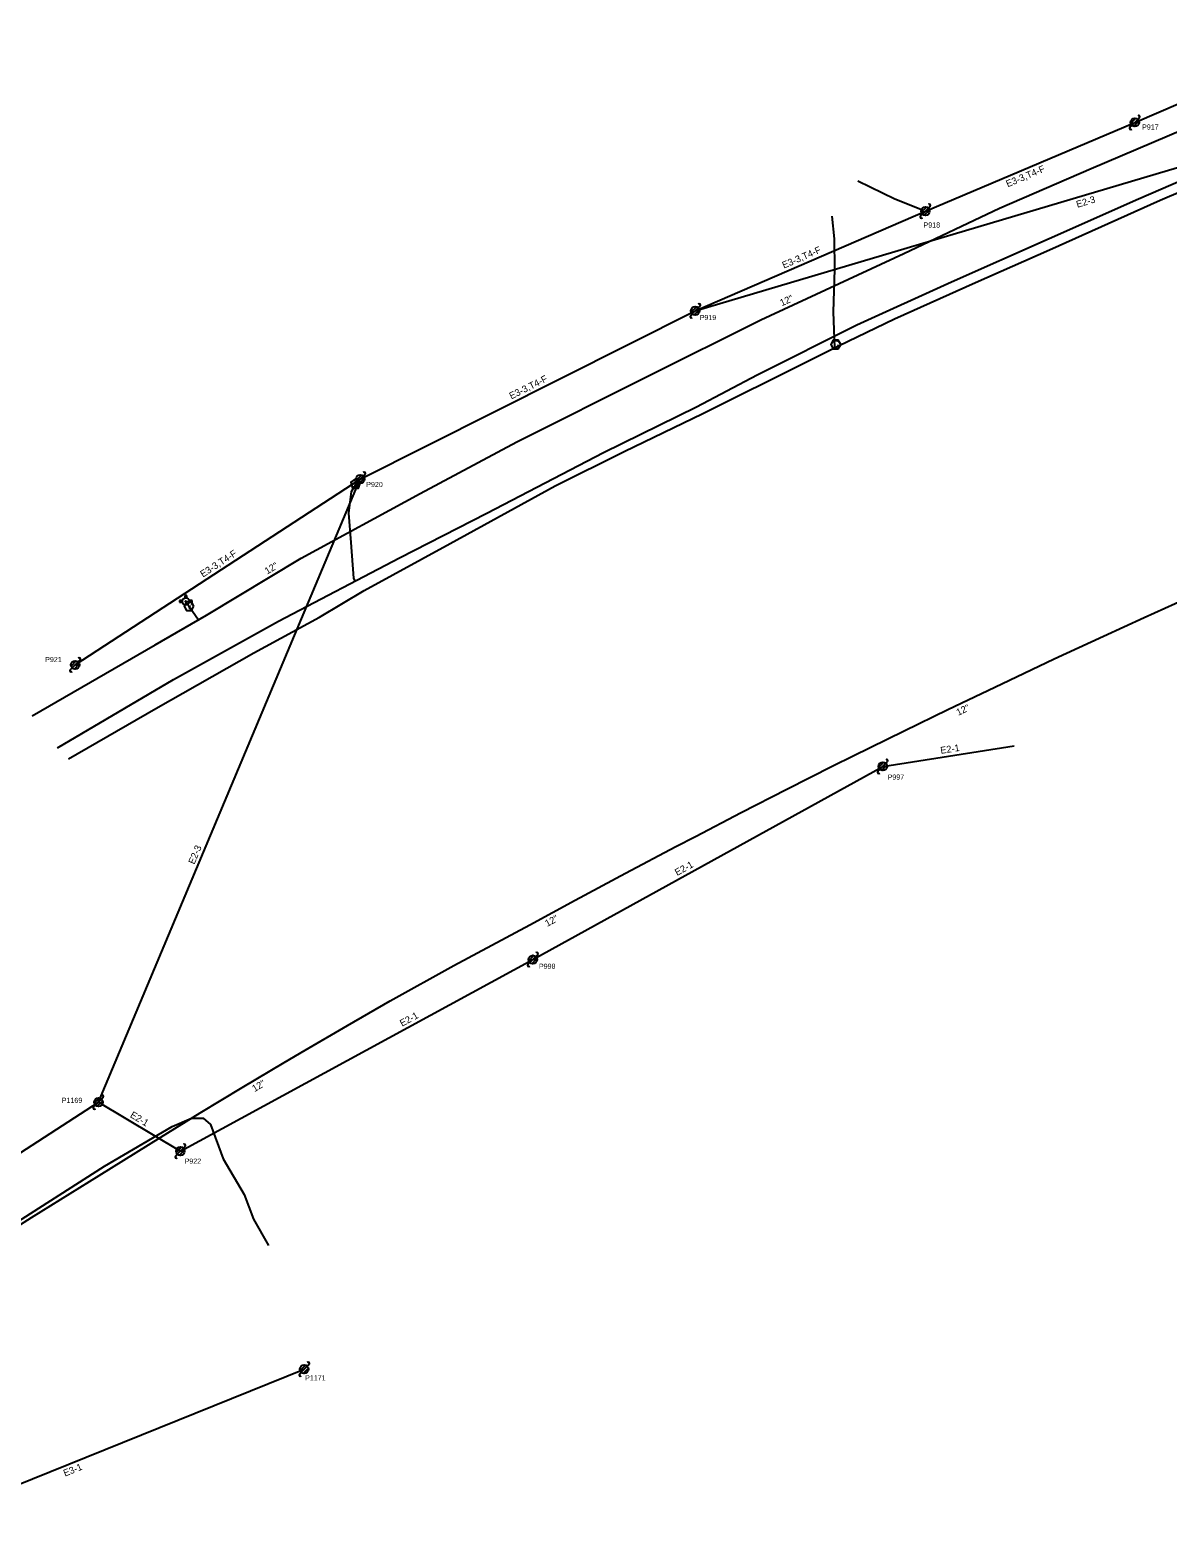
# Model space of a CAD drawing. Extents: x 1741604 to 1825760, y 1164229 to 1194908.
# Drawn here: x 1795467 to 1796131, y 1187158 to 1188039 of the extents above; entities that cross this region are included whole.
import ezdxf

# ---------------------------------------------------------------- set-up
doc = ezdxf.new("R2010")
doc.units = 0
for name, color, linetype in [('RD_EX_SU_Elec', 7, 'Continuous'), ('RD_EX_SU_Gas', 7, 'Continuous'), ('RD_EX_SU_H2O', 7, 'Continuous'), ('RD_EX_SU_Ovhd', 7, 'Continuous'), ('RD_EX_SU_Pole', 7, 'Continuous'), ('RD_EX_SU_Telecom', 7, 'Continuous'), ('RD_EX_SU_TX_H2O', 7, 'Continuous'), ('RD_EX_SU_TX_Pole', 7, 'Continuous')]:
    doc.layers.add(name, color=color, linetype=linetype)

# ---------------------------------------------------------------- blocks, each defined once
blk = doc.blocks.new('SUE_GVC')
at = {"layer": 'RD_EX_SU_Gas'}
blk.add_lwpolyline([(1.44, -2.5), (2.89, 0), (1.44, 2.5), (-1.44, 2.5), (-2.89, 0), (-1.44, -2.5)], close=True, dxfattribs=at)
blk.add_text('G', height=3.75, dxfattribs=at).set_placement((-1.34, -1.88))
blk = doc.blocks.new('SUE_WFH')
at = {"layer": 'RD_EX_SU_H2O'}
for p, q in [((-2.01, 0.6), (-3.65, 0.6)), ((-3.65, 0.6), (-3.65, -0.45)), ((-0.48, 3.38), (-0.48, 2.04)), ((0.57, 3.38), (-0.48, 3.38)), ((0.57, 2.02), (0.57, 3.38)), ((3.7, 0.6), (2.01, 0.6)), ((3.7, -0.45), (3.7, 0.6)), ((-3.65, -0.45), (-2.05, -0.45)), ((2.05, -0.45), (3.7, -0.45))]:
    blk.add_line(p, q, dxfattribs=at)
for radius in [2.1, 0.263]:
    blk.add_circle((0, 0), radius, dxfattribs=at)
for start, end in [(163.3387, 192.31502), (74.24552, 103.21276), (347.68498, 16.6613)]:
    blk.add_arc((0, 0), 2.1, start, end, dxfattribs=at)
blk = doc.blocks.new('SUE_WV')
at = {"layer": 'RD_EX_SU_H2O'}
blk.add_lwpolyline([(2.89, 0), (1.44, 2.5), (-1.44, 2.5), (-2.89, 0), (-1.44, -2.5), (1.44, -2.5)], close=True, dxfattribs=at)
blk.add_text('V', height=3.75, dxfattribs=at).set_placement((-1.43, -1.88))
blk = doc.blocks.new('SUE_TPP')
at = {"layer": 'RD_EX_SU_Telecom'}
blk.add_lwpolyline([(0, 3), (-2.85, 0.93), (-1.76, -2.43), (1.76, -2.43), (2.85, 0.93)], close=True, dxfattribs=at)
blk.add_text('T', height=3.75, dxfattribs=at).set_placement((-1.25, -1.88))
blk = doc.blocks.new('SUE_PP')
at = {"layer": 'RD_EX_SU_Pole'}
for p, q in [((-2.41, -0.65), (0.65, 2.41)), ((-1.77, -1.77), (1.77, 1.77)), ((-0.65, -2.41), (2.41, 0.65)), ((1.77, 1.77), (2.83, 2.83)), ((-2.83, -2.83), (-1.77, -1.77))]:
    blk.add_line(p, q, dxfattribs=at)
blk.add_circle((0, 0), 2.5, dxfattribs=at)
for centre, start, end in [((2.3, 3.36), 315, 135), ((-2.3, -3.36), 135, 315)]:
    blk.add_arc(centre, 0.75, start, end, dxfattribs=at)

msp = doc.modelspace()

# ---------------------------------------------------------------- linework, layer by layer
at = {"layer": 'RD_EX_SU_Elec'}
msp.add_lwpolyline([(1795950.08, 1187950.68), (1795971.83, 1187940.18), (1795988.03, 1187933.76)], dxfattribs=at)
at = {"layer": 'RD_EX_SU_Gas'}
for points in [[(1795488.96, 1187613.02), (1795539.91, 1187642.4), (1795597.23, 1187674.9), (1795635.65, 1187695.82), (1795661.69, 1187711.39), (1795712.03, 1187738.83), (1795773.39, 1187772.42), (1795813.54, 1187792.5), (1795859.65, 1187814.87), (1795920.23, 1187844.95), (1795938.97, 1187854.27), (1795971.58, 1187870.14), (1796018.89, 1187891.43), (1796062.24, 1187910.5), (1796126.94, 1187939.39), (1796190.37, 1187966.63)], [(1795936.76, 1187853.17), (1795935.91, 1187874.27), (1795936.82, 1187898.89), (1795936.56, 1187916.88), (1795935.14, 1187930.04)]]:
    msp.add_lwpolyline(points, dxfattribs=at)
at = {"layer": 'RD_EX_SU_H2O'}
msp.add_line((1795557.85, 1187704.35), (1795564.78, 1187694.15), dxfattribs=at)
for points in [[(1795893.48, 1187869.47), (1795976.99, 1187908.33), (1796032.87, 1187934.75), (1796086.58, 1187957.92), (1796204.27, 1188008.11)], [(1795467.61, 1187638.02), (1795539.65, 1187679.52), (1795569.47, 1187696.87), (1795624.81, 1187730.2), (1795694.49, 1187768.04), (1795750.95, 1187798.22), (1795827.08, 1187836.39), (1795893.48, 1187869.47)], [(1795441.87, 1187328.83), (1795467.28, 1187344.8), (1795506.82, 1187369.42), (1795542.96, 1187391.93), (1795565.85, 1187405.97), (1795590.37, 1187420.79), (1795615, 1187435.45), (1795627.19, 1187442.67), (1795651.98, 1187457.17), (1795676.85, 1187471.5), (1795714.02, 1187492.16), (1795758.42, 1187515.95), (1795785.03, 1187530.39), (1795814.38, 1187546.11), (1795843.83, 1187561.66), (1795855.23, 1187567.66), (1795881.92, 1187581.54), (1795908.7, 1187595.26), (1795935.58, 1187608.8), (1795947.42, 1187614.76), (1795977.24, 1187629.32), (1796002.78, 1187641.79), (1796034.28, 1187656.83), (1796064.82, 1187671.31), (1796093.66, 1187684.7), (1796117.41, 1187695.58), (1796147.64, 1187709.19)]]:
    msp.add_lwpolyline(points, dxfattribs=at)
at = {"layer": 'RD_EX_SU_Ovhd'}
for p, q in [((1796111.99, 1187984.95), (1796237.3, 1188038.84)), ((1795855.16, 1187874.79), (1796267.41, 1187997.51)), ((1795989.65, 1187933.06), (1796111.99, 1187984.95)), ((1795855.16, 1187874.79), (1795989.65, 1187933.06)), ((1795659.42, 1187776.35), (1795855.16, 1187874.79)), ((1795492.8, 1187667.83), (1795659.42, 1187776.35)), ((1795506.38, 1187412.31), (1795659.42, 1187776.35)), ((1795964.75, 1187608.56), (1796041.48, 1187620.47)), ((1795760.24, 1187495.61), (1795964.75, 1187608.56)), ((1795554.27, 1187383.59), (1795760.24, 1187495.61)), ((1795213.89, 1187222.6), (1795506.38, 1187412.31)), ((1795506.38, 1187412.31), (1795554.27, 1187383.59)), ((1795381.98, 1187157.65), (1795626.67, 1187256.18))]:
    msp.add_line(p, q, dxfattribs=at)
at = {"layer": 'RD_EX_SU_Pole'}
for p, q in [((1796109.58, 1187984.3), (1796112.64, 1187987.37)), ((1796110.23, 1187983.18), (1796113.76, 1187986.72)), ((1796113.76, 1187986.72), (1796114.82, 1187987.78)), ((1796109.17, 1187982.12), (1796110.23, 1187983.18)), ((1796111.35, 1187982.54), (1796114.41, 1187985.6)), ((1795987.23, 1187932.41), (1795990.29, 1187935.47)), ((1795987.88, 1187931.29), (1795991.41, 1187934.83)), ((1795989, 1187930.64), (1795992.06, 1187933.7)), ((1795991.41, 1187934.83), (1795992.47, 1187935.89)), ((1795986.82, 1187930.23), (1795987.88, 1187931.29)), ((1795852.33, 1187871.96), (1795853.39, 1187873.02)), ((1795852.74, 1187874.14), (1795855.81, 1187877.21)), ((1795853.39, 1187873.02), (1795856.93, 1187876.56)), ((1795854.51, 1187872.38), (1795857.57, 1187875.44)), ((1795856.93, 1187876.56), (1795857.99, 1187877.62)), ((1795490.38, 1187667.19), (1795493.44, 1187670.25)), ((1795491.03, 1187666.07), (1795494.57, 1187669.6)), ((1795494.57, 1187669.6), (1795495.63, 1187670.66)), ((1795489.97, 1187665.01), (1795491.03, 1187666.07)), ((1795492.15, 1187665.42), (1795495.21, 1187668.48)), ((1795962.34, 1187607.92), (1795965.4, 1187610.98)), ((1795962.98, 1187606.79), (1795966.52, 1187610.33)), ((1795964.1, 1187606.15), (1795967.17, 1187609.21)), ((1795966.52, 1187610.33), (1795967.58, 1187611.39)), ((1795961.92, 1187605.73), (1795962.98, 1187606.79)), ((1795757.42, 1187492.78), (1795758.48, 1187493.85)), ((1795757.83, 1187494.97), (1795760.89, 1187498.03)), ((1795758.48, 1187493.85), (1795762.01, 1187497.38)), ((1795759.6, 1187493.2), (1795762.66, 1187496.26)), ((1795762.01, 1187497.38), (1795763.07, 1187498.44)), ((1795503.97, 1187411.67), (1795507.03, 1187414.73)), ((1795504.62, 1187410.55), (1795508.15, 1187414.08)), ((1795505.74, 1187409.9), (1795508.8, 1187412.96)), ((1795508.15, 1187414.08), (1795509.21, 1187415.14)), ((1795503.56, 1187409.49), (1795504.62, 1187410.55)), ((1795551.44, 1187380.76), (1795552.5, 1187381.83)), ((1795551.85, 1187382.95), (1795554.92, 1187386.01)), ((1795552.5, 1187381.83), (1795556.04, 1187385.36)), ((1795553.62, 1187381.18), (1795556.68, 1187384.24)), ((1795556.04, 1187385.36), (1795557.1, 1187386.42))]:
    msp.add_line(p, q, dxfattribs=at)
for centre in [(1796111.99, 1187984.95), (1795989.65, 1187933.06), (1795855.16, 1187874.79), (1795492.8, 1187667.83), (1795964.75, 1187608.56), (1795760.24, 1187495.61), (1795506.38, 1187412.31), (1795554.27, 1187383.59)]:
    msp.add_circle(centre, 2.5, dxfattribs=at)
for centre, start, end in [((1796114.29, 1187988.31), 315, 135), ((1796109.7, 1187981.59), 135, 315), ((1795991.94, 1187936.42), 315, 135), ((1795987.35, 1187929.7), 135, 315), ((1795852.86, 1187871.43), 135, 315), ((1795857.46, 1187878.15), 315, 135), ((1795495.1, 1187671.19), 315, 135), ((1795490.5, 1187664.48), 135, 315), ((1795967.05, 1187611.92), 315, 135), ((1795962.45, 1187605.2), 135, 315), ((1795757.95, 1187492.25), 135, 315), ((1795762.54, 1187498.97), 315, 135), ((1795508.68, 1187415.67), 315, 135), ((1795504.09, 1187408.96), 135, 315), ((1795556.57, 1187386.95), 315, 135), ((1795551.97, 1187380.23), 135, 315)]:
    msp.add_arc(centre, 0.75, start, end, dxfattribs=at)
at = {"layer": 'RD_EX_SU_Telecom'}
for points in [[(1795482.43, 1187619.3), (1795550.26, 1187659.29), (1795611.69, 1187693.45), (1795682.26, 1187730.42), (1795733.3, 1187756.56), (1795801.58, 1187792.09), (1795855.9, 1187818.69), (1795891.36, 1187837.4), (1795949.66, 1187866.54), (1796004.82, 1187891.75), (1796062.08, 1187917.12), (1796114.26, 1187940.19), (1796172.33, 1187965.47)], [(1795656.44, 1187716.89), (1795655.61, 1187718.46), (1795654.03, 1187739.37), (1795652.73, 1187756.59), (1795654.19, 1187769.28), (1795656.88, 1187773.22)], [(1795260.51, 1187201.5), (1795258.59, 1187204.55), (1795257.28, 1187207.49), (1795258.33, 1187209.82), (1795284.85, 1187228.2), (1795347.31, 1187270.21), (1795400.69, 1187304.83), (1795452.1, 1187337.82), (1795509.94, 1187374.81), (1795549.48, 1187398.11), (1795560.79, 1187403), (1795567.58, 1187402.88), (1795571.9, 1187399.25), (1795579.38, 1187379.1), (1795591.53, 1187358.38), (1795597.05, 1187343.98), (1795605.79, 1187328.43)]]:
    msp.add_lwpolyline(points, dxfattribs=at)

# ---------------------------------------------------------------- block references
at = {"layer": 'RD_EX_SU_Gas'}
msp.add_blockref('SUE_GVC', (1795937.27, 1187855.11), dxfattribs=at)
at = {"layer": 'RD_EX_SU_H2O'}
for name, p in [('SUE_WFH', (1795557.42, 1187704.98)), ('SUE_WV', (1795559.31, 1187702.24))]:
    msp.add_blockref(name, p, dxfattribs=at)
at = {"layer": 'RD_EX_SU_Pole'}
for p in [(1795659.42, 1187776.35), (1795626.67, 1187256.18)]:
    msp.add_blockref('SUE_PP', p, dxfattribs=at)
at = {"layer": 'RD_EX_SU_Telecom'}
msp.add_blockref('SUE_TPP', (1795656.7, 1187773.64), dxfattribs=at)

# ---------------------------------------------------------------- texts
at = {"layer": 'RD_EX_SU_Ovhd'}
for s, rotation, p in [('E3-3,T4-F', 22.9837, (1796037.77, 1187946.95)), ('E2-3', 16.57719, (1796078.48, 1187935.01)), ('E3-3,T4-F', 23.42436, (1795906.99, 1187899.43)), ('E3-3,T4-F', 26.69969, (1795747.7, 1187822.98)), ('E3-3,T4-F', 33.07392, (1795567.48, 1187718.86)), ('E2-1', 8.82158, (1795998.72, 1187615.86)), ('E2-3', 67.19831, (1795562.45, 1187550.98)), ('E2-1', 28.91183, (1795844.57, 1187544.47)), ('E2-1', 28.53964, (1795683.85, 1187456.34)), ('E2-1', 329.0438, (1795524.55, 1187403.75)), ('E3-1', 21.93278, (1795486.85, 1187193.41))]:
    msp.add_text(s, height=4, rotation=rotation, dxfattribs=at).set_placement(p)
at = {"layer": 'RD_EX_SU_TX_H2O'}
for rotation, p in [(24.94878, (1795905.76, 1187877.39)), (31.05836, (1795605.05, 1187720.63)), (25.51492, (1796008.86, 1187638.05)), (28.4966, (1795768.68, 1187514.69)), (30.75135, (1795597.64, 1187418.14))]:
    msp.add_text('12"', height=4, rotation=rotation, dxfattribs=at).set_placement(p)
at = {"layer": 'RD_EX_SU_TX_Pole'}
for s, p in [('P917', (1796116.29, 1187980.73)), ('P918', (1795988.58, 1187923.47)), ('P919', (1795857.74, 1187869.39)), ('P920', (1795662.89, 1187771.8)), ('P921', (1795475.29, 1187669.49)), ('P997', (1795967.57, 1187600.8)), ('P998', (1795763.81, 1187490.22)), ('P1169', (1795484.97, 1187411.87)), ('P922', (1795556.75, 1187376.31)), ('P1171', (1795627.2, 1187249.67))]:
    msp.add_text(s, height=3, dxfattribs=at).set_placement(p)

doc.saveas('drawing.dxf')
